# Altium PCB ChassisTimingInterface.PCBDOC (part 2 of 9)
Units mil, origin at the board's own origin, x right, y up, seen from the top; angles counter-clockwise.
Board outline 7007.87 x 4368.85 mil, 10 copper layers (Top Layer, Int1 (GND), Int2 (Sign), Int3 (Sign), Int4 (PWR), Int5 (GND), Int6 (Sign), Int7 (Sign), Int8 (GND), Bottom Layer), stack 54.89 mil thick; 537 components, 525 nets, 2288 pads, 1306 vias.
Unrouted connection lines stored in the file: 373.
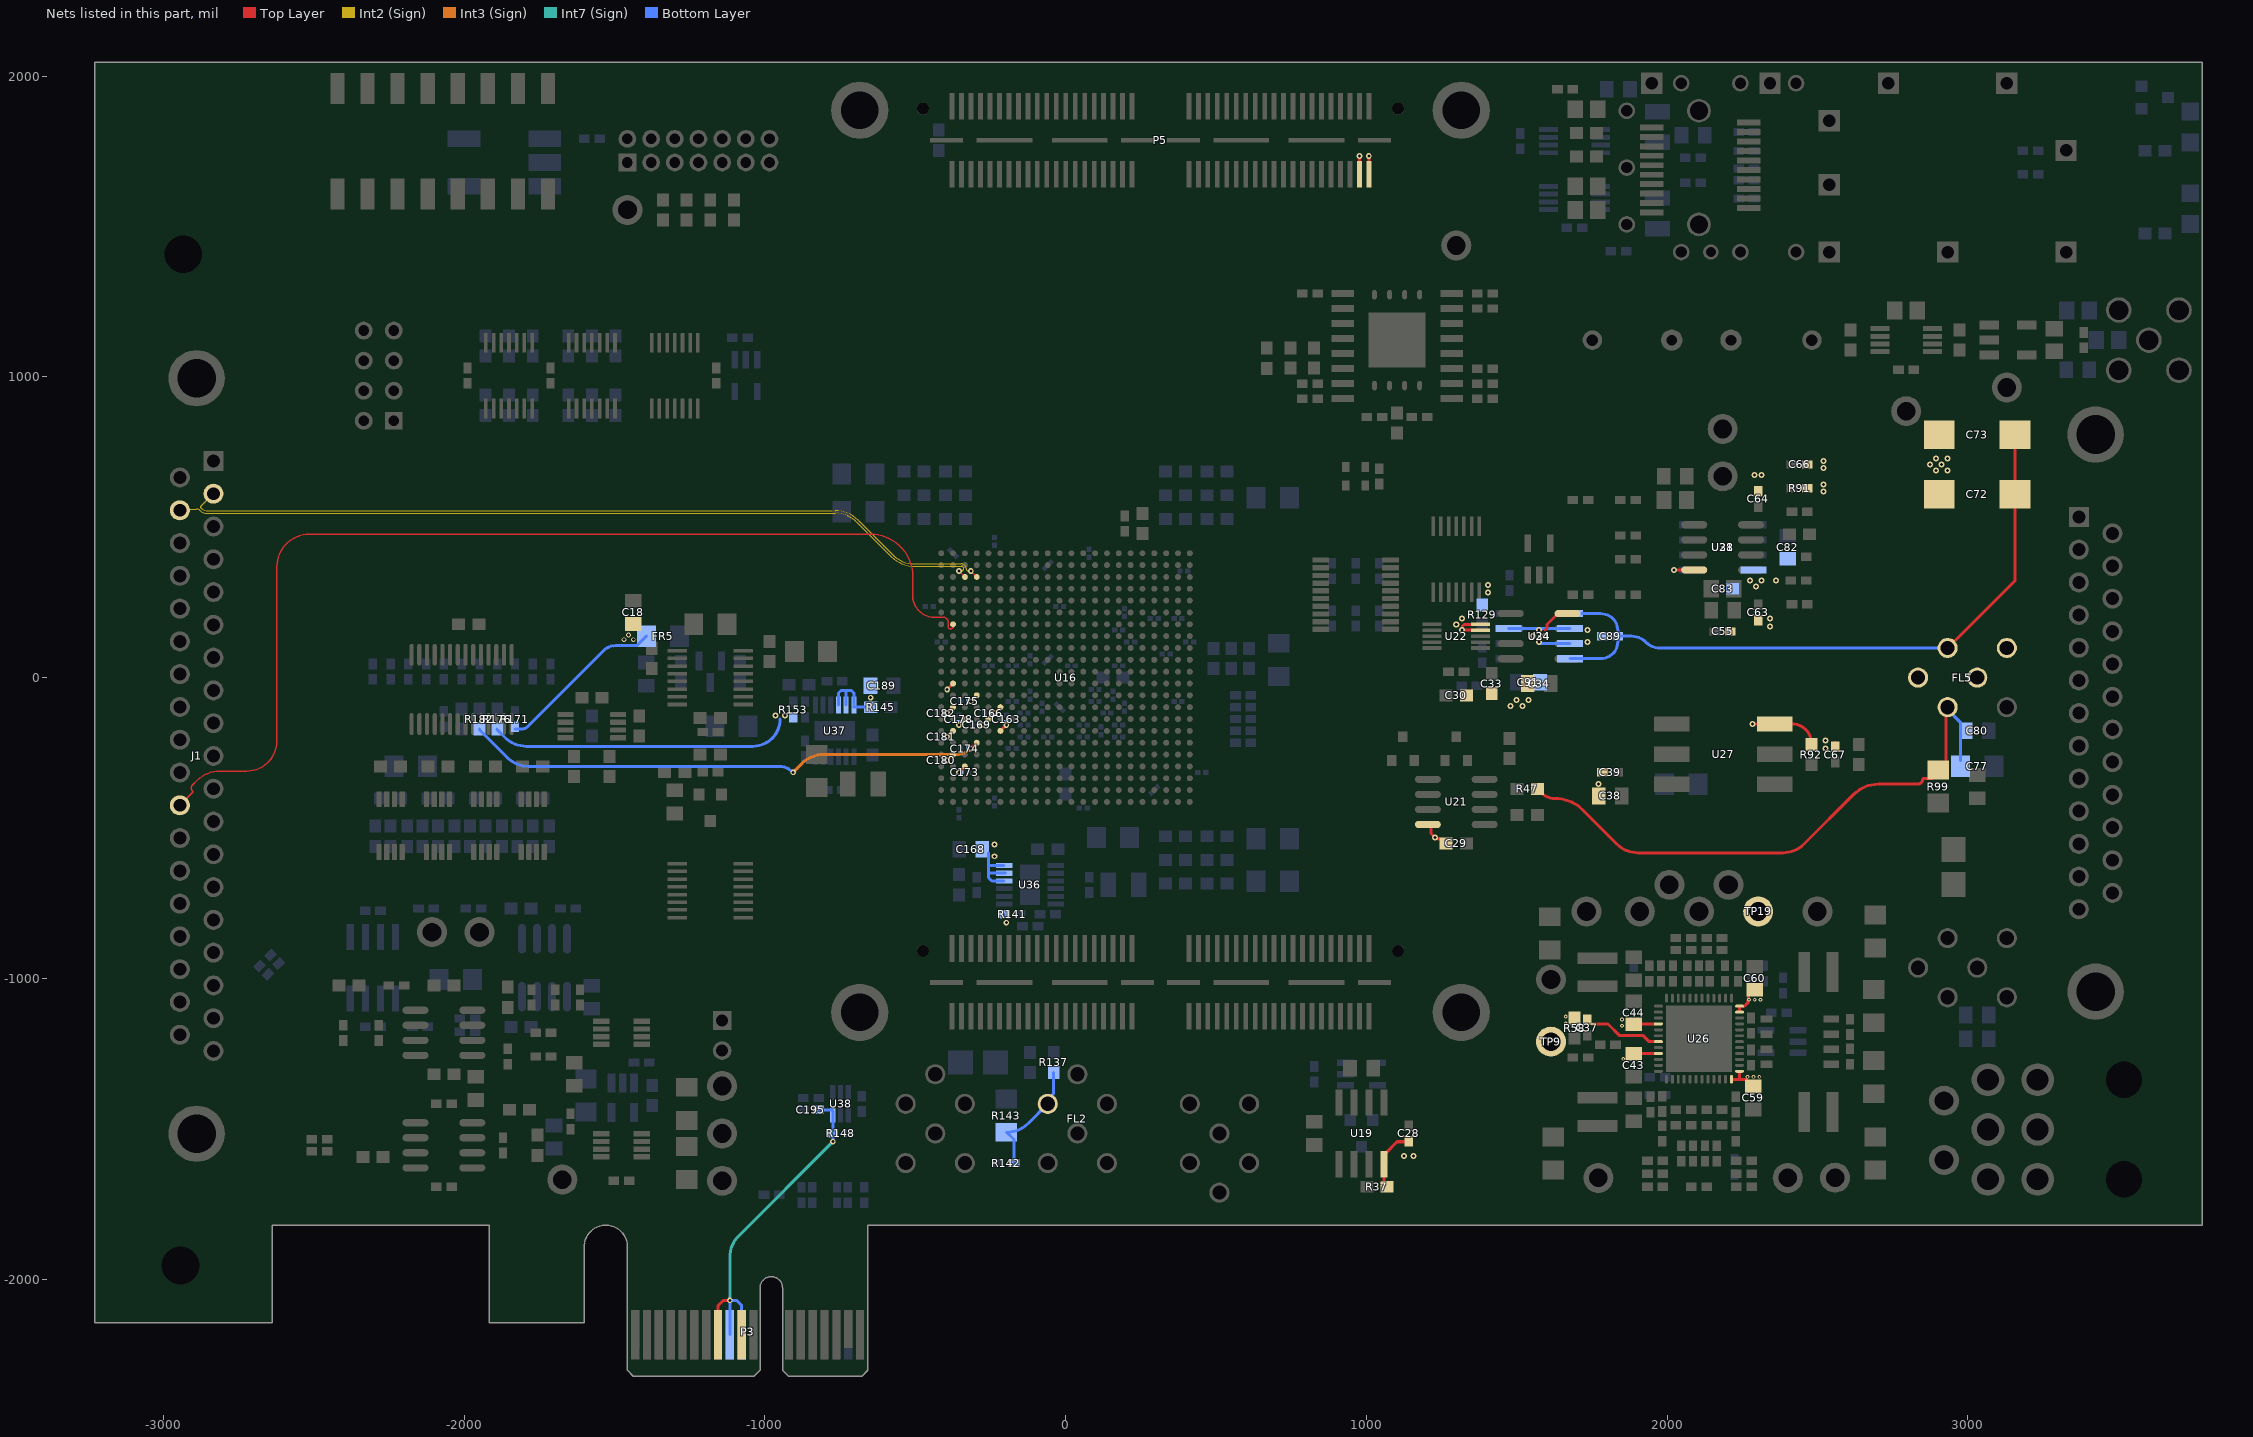
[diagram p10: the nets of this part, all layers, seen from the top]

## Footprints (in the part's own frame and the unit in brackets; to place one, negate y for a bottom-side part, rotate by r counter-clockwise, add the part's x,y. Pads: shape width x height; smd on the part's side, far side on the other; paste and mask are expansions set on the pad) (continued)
CP-48-13_L [mm] "QFN, 48-Leads, Body 7x7mm, Pitch 0.5mm, Thermal Pad 5.6x5.6mm, IPC High Density"
  oval 0.75x0.25 smd: 1(-3.425,2.75) 2(-3.425,2.25) 3(-3.425,1.75) 4(-3.425,1.25) 5(-3.425,0.75) 6(-3.425,0.25) 7(-3.425,-0.25) 8(-3.425,-0.75) 9(-3.425,-1.25) 10(-3.425,-1.75) 11(-3.425,-2.25) 12(-3.425,-2.75) 25(3.425,-2.75) 26(3.425,-2.25) 27(3.425,-1.75) 28(3.425,-1.25) 29(3.425,-0.75) 30(3.425,-0.25) 31(3.425,0.25) 32(3.425,0.75) 33(3.425,1.25) 34(3.425,1.75) 35(3.425,2.25) 36(3.425,2.75)
  oval 0.25x0.75 smd: 13(-2.75,-3.425) 14(-2.25,-3.425) 15(-1.75,-3.425) 16(-1.25,-3.425) 17(-0.75,-3.425) 18(-0.25,-3.425) 19(0.25,-3.425) 20(0.75,-3.425) 21(1.25,-3.425) 22(1.75,-3.425) 23(2.25,-3.425) 24(2.75,-3.425) 37(2.75,3.425) 38(2.25,3.425) 39(1.75,3.425) 40(1.25,3.425) 41(0.75,3.425) 42(0.25,3.425) 43(-0.25,3.425) 44(-0.75,3.425) 45(-1.25,3.425) 46(-1.75,3.425) 47(-2.25,3.425) 48(-2.75,3.425)
  rect 5.6x5.6 smd: 49(0,0)
  silkscreen extent -4.47,-3.7 3.7,3.7, body extent -3.55,-3.55 3.55,3.55, height 0.8
CR1005-0402 [mm] "Chip Resistor; Body 1.1 x 0.5 mm (LxW typ)"
  rect 0.9x0.7 smd: 1(-0.65,0) 2(0.65,0)
  body extent -0.5,-0.25 0.5,0.25, height 0.32
CR1608-0603 [mm] "Chip Resistor; Body 1.6 x 0.8 mm (LxW typ)"
  rect 1.1x1 smd: 1(-0.85,0) 2(0.85,0)
  body extent -0.76,-0.43 0.79,0.42, height 0.46
CR2012-0805 [mm] "Chip Resistor; Body 2.0 x 1.3 mm (LxW typ)"
  rect 1.3x1.5 smd: 1(-0.95,0) 2(0.95,0)
  body extent -1,-0.62 1,0.63, height 0.46
DB25F-RA [mm] "Receptiacle; D Subminiature 25 Position; Right Angle"
  rect 1.69x1.69 hole 1.09: 1(-16.566,-1.42)
  round 1.69 hole 1.09: 2(-13.805,-1.42) 3(-11.044,-1.42) 4(-8.283,-1.42) 5(-5.522,-1.42) 6(-2.761,-1.42) 7(0,-1.42) 8(2.761,-1.42) 9(5.522,-1.42) 10(8.283,-1.42) 11(11.044,-1.42) 12(13.805,-1.42) 13(16.566,-1.42) 14(-15.185,1.42) 15(-12.424,1.42) 16(-9.663,1.42) 17(-6.902,1.42) 18(-4.142,1.42) 19(-1.381,1.42) 20(1.381,1.42) 21(4.142,1.42) 22(6.903,1.42) 23(9.664,1.42) 24(12.425,1.42) 25(15.186,1.42)
  round 4.76 hole 3.26: 26(-23.526,0) 27(23.526,0)
  silkscreen extent -26.5,-3 26.6,9.5, body extent -26.59,-3.18 26.49,15.72, height 12.62
DB37M-RA [mm] "Plug; D Subminiature 37 Position; Right Angle"
  rect 1.69x1.69 hole 1.09: 1(24.917,-1.42)
  round 1.69 hole 1.09: 2(22.149,-1.42) 3(19.38,-1.42) 4(16.612,-1.42) 5(13.843,-1.42) 6(11.074,-1.42) 7(8.306,-1.42) 8(5.537,-1.42) 9(2.769,-1.42) 10(0,-1.42) 11(-2.769,-1.42) 12(-5.537,-1.42) 13(-8.306,-1.42) 14(-11.074,-1.42) 15(-13.843,-1.42) 16(-16.612,-1.42) 17(-19.38,-1.42) 18(-22.149,-1.42) 19(-24.917,-1.42) 20(23.52,1.42) 21(20.752,1.42) 22(17.983,1.42) 23(15.215,1.42) 24(12.446,1.42) 25(9.677,1.42) 26(6.909,1.42) 27(4.14,1.42) 28(1.372,1.42) 29(-1.397,1.42) 30(-4.166,1.42) 31(-6.934,1.42) 32(-9.703,1.42) 33(-12.471,1.42) 34(-15.24,1.42) 35(-18.009,1.42) 36(-20.777,1.42) 37(-23.546,1.42)
  round 4.76 hole 3.26: 38(31.902,0) 39(-31.902,0)
  silkscreen extent -35.08,-3.05 35.08,9.52, body extent -34.77,-3.24 34.77,15.37, height 12.62
DGK0008A_N [mm] "TSOP, 8-Leads, Body 3.1x3.1mm, Pitch 0.65mm, IPC Medium Density"
  rrect22% 1.35x0.45 smd: 1(-2.225,0.975) 2(-2.225,0.325) 3(-2.225,-0.325) 4(-2.225,-0.975) 5(2.225,-0.975) 6(2.225,-0.325) 7(2.225,0.325) 8(2.225,0.975)
  silkscreen extent -2.35,-1.55 1.15,1.9, body extent -2.45,-1.5 2.45,1.5, height 0.94
DIP_SW_8WAY_SMD_SIDE [mm] "DIP Switch; 16 Leads, right-angle"
  rect 1.2x2.6 smd: 1(-8.89,-4.45) 2(-6.35,-4.45) 3(-3.81,-4.45) 4(-1.27,-4.45) 5(1.27,-4.45) 6(3.81,-4.45) 7(6.35,-4.45) 8(8.89,-4.45) 9(8.89,4.45) 10(6.35,4.45) 11(3.81,4.45) 12(1.27,4.45) 13(-1.27,4.45) 14(-3.81,4.45) 15(-6.35,4.45) 16(-8.89,4.45)
  silkscreen extent -10.29,-2.5 10.31,2.5, body extent -11.15,-6.5 11.15,4.65, height 6.98
ECQPZ120060-5.0 [mm] "Polypropylene Film Capacitor; Body 12.0 x 6.0 mm (LxW typ); 5.0mm lead spacing"
  round 1.8 hole 0.9: 1(0,0) 2(5,0)
  silkscreen extent -3.5,-3 8.5,3
FGG484 [mm] "BGA, 484-Balls, Body 23x23mm, Pitch 1mm"
  round 0.5 smd: A1(-10.5,10.5) A2(-9.5,10.5) A3(-8.5,10.5) A4(-7.5,10.5) A5(-6.5,10.5) A6(-5.5,10.5) A7(-4.5,10.5) A8(-3.5,10.5) A9(-2.5,10.5) A10(-1.5,10.5) A11(-0.5,10.5) A12(0.5,10.5) A13(1.5,10.5) A14(2.5,10.5) A15(3.5,10.5) A16(4.5,10.5) A17(5.5,10.5) A18(6.5,10.5) A19(7.5,10.5) A20(8.5,10.5) A21(9.5,10.5) A22(10.5,10.5) AA1(-10.5,-9.5) AA2(-9.5,-9.5) AA3(-8.5,-9.5) AA4(-7.5,-9.5) AA5(-6.5,-9.5) AA6(-5.5,-9.5) AA7(-4.5,-9.5) AA8(-3.5,-9.5) AA9(-2.5,-9.5) AA10(-1.5,-9.5) AA11(-0.5,-9.5) AA12(0.5,-9.5) AA13(1.5,-9.5) AA14(2.5,-9.5) AA15(3.5,-9.5) AA16(4.5,-9.5) AA17(5.5,-9.5) AA18(6.5,-9.5) AA19(7.5,-9.5) AA20(8.5,-9.5) AA21(9.5,-9.5) AA22(10.5,-9.5) AB1(-10.5,-10.5) AB2(-9.5,-10.5) AB3(-8.5,-10.5) AB4(-7.5,-10.5) AB5(-6.5,-10.5) AB6(-5.5,-10.5) AB7(-4.5,-10.5) AB8(-3.5,-10.5) AB9(-2.5,-10.5) AB10(-1.5,-10.5) AB11(-0.5,-10.5) AB12(0.5,-10.5) AB13(1.5,-10.5) AB14(2.5,-10.5) AB15(3.5,-10.5) AB16(4.5,-10.5) AB17(5.5,-10.5) AB18(6.5,-10.5) AB19(7.5,-10.5) AB20(8.5,-10.5) AB21(9.5,-10.5) AB22(10.5,-10.5) B1(-10.5,9.5) B2(-9.5,9.5) B3(-8.5,9.5) B4(-7.5,9.5) B5(-6.5,9.5) B6(-5.5,9.5) B7(-4.5,9.5) B8(-3.5,9.5) B9(-2.5,9.5) B10(-1.5,9.5) B11(-0.5,9.5) B12(0.5,9.5) B13(1.5,9.5) B14(2.5,9.5) B15(3.5,9.5) B16(4.5,9.5) B17(5.5,9.5) B18(6.5,9.5) B19(7.5,9.5) B20(8.5,9.5) B21(9.5,9.5) B22(10.5,9.5) C1(-10.5,8.5) C2(-9.5,8.5) C3(-8.5,8.5) C4(-7.5,8.5) C5(-6.5,8.5) C6(-5.5,8.5) C7(-4.5,8.5) C8(-3.5,8.5) C9(-2.5,8.5) C10(-1.5,8.5) C11(-0.5,8.5) C12(0.5,8.5) C13(1.5,8.5) C14(2.5,8.5) C15(3.5,8.5) C16(4.5,8.5) C17(5.5,8.5) C18(6.5,8.5) C19(7.5,8.5) C20(8.5,8.5) C21(9.5,8.5) C22(10.5,8.5) D1(-10.5,7.5) D2(-9.5,7.5) D3(-8.5,7.5) D4(-7.5,7.5) D5(-6.5,7.5) D6(-5.5,7.5) D7(-4.5,7.5) D8(-3.5,7.5) D9(-2.5,7.5) D10(-1.5,7.5) D11(-0.5,7.5) D12(0.5,7.5) D13(1.5,7.5) D14(2.5,7.5) D15(3.5,7.5) D16(4.5,7.5) D17(5.5,7.5) D18(6.5,7.5) D19(7.5,7.5) D20(8.5,7.5) D21(9.5,7.5) D22(10.5,7.5) E1(-10.5,6.5) E2(-9.5,6.5) E3(-8.5,6.5) E4(-7.5,6.5) E5(-6.5,6.5) E6(-5.5,6.5) E7(-4.5,6.5) E8(-3.5,6.5) E9(-2.5,6.5) E10(-1.5,6.5) E11(-0.5,6.5) E12(0.5,6.5) E13(1.5,6.5) E14(2.5,6.5) E15(3.5,6.5) E16(4.5,6.5) E17(5.5,6.5) E18(6.5,6.5) E19(7.5,6.5) E20(8.5,6.5) E21(9.5,6.5) E22(10.5,6.5) F1(-10.5,5.5) F2(-9.5,5.5) F3(-8.5,5.5) F4(-7.5,5.5) F5(-6.5,5.5) F6(-5.5,5.5) F7(-4.5,5.5) F8(-3.5,5.5) F9(-2.5,5.5) F10(-1.5,5.5) F11(-0.5,5.5) F12(0.5,5.5) F13(1.5,5.5) F14(2.5,5.5) F15(3.5,5.5) F16(4.5,5.5) F17(5.5,5.5) F18(6.5,5.5) F19(7.5,5.5) F20(8.5,5.5) F21(9.5,5.5) F22(10.5,5.5) G1(-10.5,4.5) G2(-9.5,4.5) G3(-8.5,4.5) G4(-7.5,4.5) G5(-6.5,4.5) G6(-5.5,4.5) G7(-4.5,4.5) G8(-3.5,4.5) G9(-2.5,4.5) G10(-1.5,4.5) G11(-0.5,4.5) G12(0.5,4.5) G13(1.5,4.5) G14(2.5,4.5) G15(3.5,4.5) G16(4.5,4.5) G17(5.5,4.5) G18(6.5,4.5) G19(7.5,4.5) G20(8.5,4.5) G21(9.5,4.5) G22(10.5,4.5) H1(-10.5,3.5) H2(-9.5,3.5) H3(-8.5,3.5) H4(-7.5,3.5) H5(-6.5,3.5) H6(-5.5,3.5) H7(-4.5,3.5) H8(-3.5,3.5) H9(-2.5,3.5) H10(-1.5,3.5) H11(-0.5,3.5) H12(0.5,3.5) H13(1.5,3.5) H14(2.5,3.5) H15(3.5,3.5) H16(4.5,3.5) H17(5.5,3.5) H18(6.5,3.5) H19(7.5,3.5) H20(8.5,3.5) H21(9.5,3.5) H22(10.5,3.5) J1(-10.5,2.5) J2(-9.5,2.5) J3(-8.5,2.5) J4(-7.5,2.5) J5(-6.5,2.5) J6(-5.5,2.5) J7(-4.5,2.5) J8(-3.5,2.5) J9(-2.5,2.5) J10(-1.5,2.5) J11(-0.5,2.5) J12(0.5,2.5) J13(1.5,2.5) J14(2.5,2.5) J15(3.5,2.5) J16(4.5,2.5) J17(5.5,2.5) J18(6.5,2.5) J19(7.5,2.5) J20(8.5,2.5) J21(9.5,2.5) J22(10.5,2.5) K1(-10.5,1.5) K2(-9.5,1.5) K3(-8.5,1.5) K4(-7.5,1.5) K5(-6.5,1.5) K6(-5.5,1.5) K7(-4.5,1.5) K8(-3.5,1.5) K9(-2.5,1.5) K10(-1.5,1.5) K11(-0.5,1.5) K12(0.5,1.5) K13(1.5,1.5) K14(2.5,1.5) K15(3.5,1.5) K16(4.5,1.5) K17(5.5,1.5) K18(6.5,1.5) K19(7.5,1.5) K20(8.5,1.5) K21(9.5,1.5) K22(10.5,1.5) L1(-10.5,0.5) L2(-9.5,0.5) L3(-8.5,0.5) L4(-7.5,0.5) L5(-6.5,0.5) L6(-5.5,0.5) L7(-4.5,0.5) L8(-3.5,0.5) L9(-2.5,0.5) L10(-1.5,0.5) L11(-0.5,0.5) L12(0.5,0.5) L13(1.5,0.5) L14(2.5,0.5) L15(3.5,0.5) L16(4.5,0.5) L17(5.5,0.5) L18(6.5,0.5) L19(7.5,0.5) L20(8.5,0.5) L21(9.5,0.5) L22(10.5,0.5) M1(-10.5,-0.5) M2(-9.5,-0.5) M3(-8.5,-0.5) M4(-7.5,-0.5) M5(-6.5,-0.5) M6(-5.5,-0.5) M7(-4.5,-0.5) M8(-3.5,-0.5) M9(-2.5,-0.5) M10(-1.5,-0.5) M11(-0.5,-0.5) M12(0.5,-0.5) M13(1.5,-0.5) M14(2.5,-0.5) M15(3.5,-0.5) M16(4.5,-0.5) M17(5.5,-0.5) M18(6.5,-0.5) M19(7.5,-0.5) M20(8.5,-0.5) M21(9.5,-0.5) M22(10.5,-0.5) N1(-10.5,-1.5) N2(-9.5,-1.5) N3(-8.5,-1.5) N4(-7.5,-1.5) N5(-6.5,-1.5) N6(-5.5,-1.5) N7(-4.5,-1.5) N8(-3.5,-1.5) N9(-2.5,-1.5) N10(-1.5,-1.5) N11(-0.5,-1.5) N12(0.5,-1.5) N13(1.5,-1.5) N14(2.5,-1.5) N15(3.5,-1.5) N16(4.5,-1.5) N17(5.5,-1.5) N18(6.5,-1.5) N19(7.5,-1.5) N20(8.5,-1.5) N21(9.5,-1.5) N22(10.5,-1.5) P1(-10.5,-2.5) P2(-9.5,-2.5) P3(-8.5,-2.5) P4(-7.5,-2.5) P5(-6.5,-2.5) P6(-5.5,-2.5) P7(-4.5,-2.5) P8(-3.5,-2.5) P9(-2.5,-2.5) P10(-1.5,-2.5) P11(-0.5,-2.5) P12(0.5,-2.5) P13(1.5,-2.5) P14(2.5,-2.5) P15(3.5,-2.5) P16(4.5,-2.5) P17(5.5,-2.5) P18(6.5,-2.5) P19(7.5,-2.5) P20(8.5,-2.5) P21(9.5,-2.5) P22(10.5,-2.5) R1(-10.5,-3.5) R2(-9.5,-3.5) R3(-8.5,-3.5) R4(-7.5,-3.5) R5(-6.5,-3.5) R6(-5.5,-3.5) R7(-4.5,-3.5) R8(-3.5,-3.5) R9(-2.5,-3.5) R10(-1.5,-3.5) R11(-0.5,-3.5) R12(0.5,-3.5) R13(1.5,-3.5) R14(2.5,-3.5) R15(3.5,-3.5) R16(4.5,-3.5) R17(5.5,-3.5) R18(6.5,-3.5) R19(7.5,-3.5) R20(8.5,-3.5) R21(9.5,-3.5) R22(10.5,-3.5) T1(-10.5,-4.5) T2(-9.5,-4.5) T3(-8.5,-4.5) T4(-7.5,-4.5) T5(-6.5,-4.5) T6(-5.5,-4.5) T7(-4.5,-4.5) T8(-3.5,-4.5) T9(-2.5,-4.5) T10(-1.5,-4.5) T11(-0.5,-4.5) T12(0.5,-4.5) T13(1.5,-4.5) T14(2.5,-4.5) T15(3.5,-4.5) T16(4.5,-4.5) T17(5.5,-4.5) T18(6.5,-4.5) T19(7.5,-4.5) T20(8.5,-4.5) T21(9.5,-4.5) T22(10.5,-4.5) U1(-10.5,-5.5) U2(-9.5,-5.5) U3(-8.5,-5.5) U4(-7.5,-5.5) U5(-6.5,-5.5) U6(-5.5,-5.5) U7(-4.5,-5.5) U8(-3.5,-5.5) U9(-2.5,-5.5) U10(-1.5,-5.5) U11(-0.5,-5.5) U12(0.5,-5.5) U13(1.5,-5.5) U14(2.5,-5.5) U15(3.5,-5.5) U16(4.5,-5.5) U17(5.5,-5.5) U18(6.5,-5.5) U19(7.5,-5.5) U20(8.5,-5.5) U21(9.5,-5.5) U22(10.5,-5.5) V1(-10.5,-6.5) V2(-9.5,-6.5) V3(-8.5,-6.5) V4(-7.5,-6.5) V5(-6.5,-6.5) V6(-5.5,-6.5) V7(-4.5,-6.5) V8(-3.5,-6.5) V9(-2.5,-6.5) V10(-1.5,-6.5) V11(-0.5,-6.5) V12(0.5,-6.5) V13(1.5,-6.5) V14(2.5,-6.5) V15(3.5,-6.5) V16(4.5,-6.5) V17(5.5,-6.5) V18(6.5,-6.5) V19(7.5,-6.5) V20(8.5,-6.5) V21(9.5,-6.5) V22(10.5,-6.5) W1(-10.5,-7.5) W2(-9.5,-7.5) W3(-8.5,-7.5) W4(-7.5,-7.5) W5(-6.5,-7.5) W6(-5.5,-7.5) W7(-4.5,-7.5) W8(-3.5,-7.5) W9(-2.5,-7.5) W10(-1.5,-7.5) W11(-0.5,-7.5) W12(0.5,-7.5) W13(1.5,-7.5) W14(2.5,-7.5) W15(3.5,-7.5) W16(4.5,-7.5) W17(5.5,-7.5) W18(6.5,-7.5) W19(7.5,-7.5) W20(8.5,-7.5) W21(9.5,-7.5) W22(10.5,-7.5) Y1(-10.5,-8.5) Y2(-9.5,-8.5) Y3(-8.5,-8.5) Y4(-7.5,-8.5) Y5(-6.5,-8.5) Y6(-5.5,-8.5) Y7(-4.5,-8.5) Y8(-3.5,-8.5) Y9(-2.5,-8.5) Y10(-1.5,-8.5) Y11(-0.5,-8.5) Y12(0.5,-8.5) Y13(1.5,-8.5) Y14(2.5,-8.5) Y15(3.5,-8.5) Y16(4.5,-8.5) Y17(5.5,-8.5) Y18(6.5,-8.5) Y19(7.5,-8.5) Y20(8.5,-8.5) Y21(9.5,-8.5) Y22(10.5,-8.5)
  silkscreen extent -12.27,-11.5 11.5,11.5, body extent -11.5,-11.5 11.5,11.5, height 2.6
FP-002-15547-MFG [mm]
  rect 1.9x0.6 smd: 1(-4.6,4.445) 2(-4.6,3.175) 3(-4.6,1.905) 4(-4.6,0.635) 5(-4.6,-0.635) 6(-4.6,-1.905) 7(-4.6,-3.175) 8(-4.6,-4.445) 9(4.6,-4.445) 10(4.6,-3.175) 11(4.6,-1.905) 12(4.6,-0.635) 13(4.6,0.635) 14(4.6,1.905) 15(4.6,3.175) 16(4.6,4.445)
  silkscreen extent -6.25,-5.25 2.8,5.25, body extent -5.65,-5.5 5.65,5.5, height 0.25
FP-CDFN2520-4LD-PL-1-MFG [mm]
  rect 0.85x0.65 smd paste+0 mask+0: 1(-0.775,0.825) 2(-0.775,-0.825) 3(0.775,-0.825) 4(0.775,0.825)
  silkscreen extent -1.92,-0.13 1.02,0.95, body extent -1.3,-1.38 1.3,1.38, height 0.25
FP-XAL40-MFG [mm]
  rect 0.98x3.4 smd: 1(-1.185,0) 2(1.185,0)
  silkscreen extent -2.15,-2.15 2.15,2.15, body extent -2.25,-2.25 2.25,2.25, height 0.25
KING-LED2107-13-RED-2_V [mm] "LED, Right Angle SMT, 2.1x0.7mm, 1.3mm Thickness, Pad 1 Cathode"
  rect 1.5x1.5 smd paste+0 mask+0: 1(1.3,0) 2(-1.3,0)
  silkscreen extent 2.35,-0.64 2.35,0.63, body extent -1.05,-0.4 1.05,0.9, height 0.67
LED-0805 [mm] "SMD LED, 805, Body 2.0 x 1.3 mm (LxW typ)"
  rect 1.15x1.4 smd: 1(-0.975,0) 2(0.975,0)
  silkscreen extent -1.85,-0.6 -1.85,0.6, body extent -1,-0.62 1,0.63, height 0.75
LIGO-LOGO-SM [mil] "Smaller Ligo Logo"
  silkscreen extent -154,4 -36,122
LT-S5-5-TSOT-23_M [mm] "SOT23, 5-Leads, Body 2.90x1.63mm, Pitch 0.95mm, IPC Low Density"
  rect 1.6x0.65 smd: 1(-1.25,0.95) 2(-1.25,0) 3(-1.25,-0.95) 4(1.25,-0.95) 5(1.25,0.95)
  silkscreen extent -1.37,-1.45 0.05,1.95, body extent -0.87,-1.45 0.87,1.45, height 1
MCSM-DO-214BA-2_L [mm] "Molded, 2-Leads, Body 4.57x3.94mm, IPC High Density"
  rect 2.1x2.05 smd: 1(-1.475,0) 2(1.475,0)
  silkscreen extent -2.3,-2 3.03,2, body extent -2.5,-1.97 2.51,1.97, height 3.3
MSA/SFP2x10 [mm] "Multi Source Agreement, Small Factor Plugable"
  rect 2x0.5 smd: 1(0,0) 2(0,-0.8) 3(0,-1.6) 4(0,-2.4) 5(0,-3.2) 6(0,-4) 7(0,-4.8) 8(0,-5.6) 9(0,-6.4) 10(0,-7.2) 11(8.2,-6.8) 12(8.2,-6) 13(8.2,-5.2) 14(8.2,-4.4) 15(8.2,-3.6) 16(8.2,-2.8) 17(8.2,-2) 18(8.2,-1.2) 19(8.2,-0.4) 20(8.2,0.4)
  rect 1.8x1.8 hole 1.05: 21(-26.8,-4.85) 21(-26.8,3.73) 21(-21.8,-10.53) 21(-16.8,3.73) 21(-11.8,-10.53) 21(-6.8,-1.95) 21(-6.8,3.73) 21(-6.8,-7.35) 21(-1.8,-10.53) 21(8.2,-10.53)
  round 1.4 hole 0.95: 22(-4,3.73) 22(-4,-10.53) 22(0.7,3.73) 22(0.7,-10.53) 22(5.7,3.73) 22(5.7,-10.53) 22(10.3,-3.4) 22(10.3,1.4) 22(10.3,-8.2)
  round 2 hole 1.55: 23(4.2,1.4) 23(4.2,-8.2)
  round 1.3 hole 0.85: 24(3.2,3.73)
  silkscreen extent -31.2,-11.43 10.9,4.63, body extent -38.26,-11.3 10.54,4.54, height 10.83
MSOP8 [mm] "MSOP Plastic Small-Outline Package"
  rect 0.42x1.6 smd: 1(-0.975,-2.205) 2(-0.325,-2.205) 3(0.325,-2.205) 4(0.975,-2.205) 5(0.975,2.195) 6(0.325,2.195) 7(-0.325,2.195) 8(-0.975,2.195)
  silkscreen extent -1.3,-0.77 1.3,0.76, body extent -1.5,-2.45 1.5,2.45, height 1.15
MSOP12_PAD [mil] "MSOP 12 with pad"
  rect 55x17 smd: 1(-86,63.98) 2(-86,38.39) 3(-86,12.8) 4(-86,-12.8) 5(-86,-38.39) 6(-86,-63.98) 7(86,-63.98) 8(86,-38.39) 9(86,-12.8) 10(86,12.8) 11(86,38.39) 12(86,63.98)
  rect 65x133.86 smd: 13(0,0)
  silkscreen extent -53,-84 134,84, body extent -99,-79 99,79, height 67
MURA-BNX016-01_V [mm] "THD, 6-Leads, Body 12x11mm"
  round 1.7 hole 1.2: 1(-2.5,2.5) 2(2.5,2.5) 3(-2.5,-2.5) 4(2.5,-2.5) 5(0,0) 6(0,5)
  silkscreen extent -6.29,-6 5.5,6, body extent -5.5,-6 5.5,6, height 8
NETTIE1_BOTH [mm] "Tie two nets together"
  rect 1.575x1.575 hole 1.016: 1(0,0)
  round 1.575 hole 1.016: 2(2.54,0)
  Top Layer region: -1.016,-1.015 3.556,-1.015 3.556,1.017 -1.016,1.017
  Bottom Layer region: -1.016,-1.015 3.556,-1.015 3.556,1.017 -1.016,1.017
NETTIE1_SMDTOP [mil] "Tie two nets together"
  rect 10x10 smd mask-10: 1(0,0) 2(20,0)
  Top Layer region: -10,10 30,10 30,-10 -10,-10
ONSC-SOT-23-3-318-08_V [mm] "SOT23, 3-Leads, Body 2.92x1.3mm, Pitch 0.95mm"
  rect 0.9x0.8 smd: 1(-1,0.95) 2(-1,-0.95) 3(1,0)
  silkscreen extent -1.12,-1.46 0.65,2.02, body extent -0.65,-1.46 0.65,1.46, height 1.11
PCIeX1-GF-2D-1000-1K-O36 [mm] "Golden finger, PCIeX1, Dual, Opposite, Pitch 1mm, 36-Position"
  rect 0.7x3.2 smd far side: A1(-9.5,0.5)
  rect 0.7x4.2 smd far side: A2(-8.5,0) A3(-7.5,0) A4(-6.5,0) A5(-5.5,0) A6(-4.5,0) A7(-3.5,0) A8(-2.5,0) A9(-1.5,0) A10(-0.5,0) A11(0.5,0) A12(3.5,0) A13(4.5,0) A14(5.5,0) A15(6.5,0) A16(7.5,0) A17(8.5,0) A18(9.5,0)
  rect 0.7x4.2 smd: B1(-9.5,0) B2(-8.5,0) B3(-7.5,0) B4(-6.5,0) B5(-5.5,0) B6(-4.5,0) B7(-3.5,0) B8(-2.5,0) B9(-1.5,0) B10(-0.5,0) B11(0.5,0) B12(3.5,0) B13(4.5,0) B14(5.5,0) B15(6.5,0) B16(7.5,0) B18(9.5,0)
  rect 0.7x3.2 smd: B17(8.5,0.5)
PW0020A_N [mm] "SOP, 20-Leads, Body 6.6x4.5mm, Pitch 0.65mm, IPC Medium Density"
  rrect22% 1.4x0.45 smd: 1(-2.95,2.925) 2(-2.95,2.275) 3(-2.95,1.625) 4(-2.95,0.975) 5(-2.95,0.325) 6(-2.95,-0.325) 7(-2.95,-0.975) 8(-2.95,-1.625) 9(-2.95,-2.275) 10(-2.95,-2.925) 11(2.95,-2.925) 12(2.95,-2.275) 13(2.95,-1.625) 14(2.95,-0.975) 15(2.95,-0.325) 16(2.95,0.325) 17(2.95,0.975) 18(2.95,1.625) 19(2.95,2.275) 20(2.95,2.925)
  silkscreen extent -3.07,-3.3 1.85,3.82, body extent -3.21,-3.25 3.21,3.25, height 1
QSE040 [mil] "Samtec hi-speed socket, 0.8mm, QSE series, 80 pins"
  rect 16x89 smd: 1(-692.9,-112.78) 2(-692.9,112.78) 3(-661.42,-112.78) 4(-661.42,112.78) 5(-629.92,-112.78) 6(-629.92,112.78) 7(-598.42,-112.78) 8(-598.42,112.78) 9(-566.92,-112.78) 10(-566.92,112.78) 11(-535.42,-112.78) 12(-535.42,112.78) 13(-503.93,-112.78) 14(-503.93,112.78) 15(-472.43,-112.78) 16(-472.43,112.78) 17(-440.93,-112.78) 18(-440.93,112.78) 19(-409.43,-112.78) 20(-409.43,112.78) 21(-377.95,-112.78) 22(-377.95,112.78) 23(-346.45,-112.78) 24(-346.45,112.78) 25(-314.95,-112.78) 26(-314.95,112.78) 27(-283.45,-112.78) 28(-283.45,112.78) 29(-251.97,-112.78) 30(-251.97,112.78) 31(-220.47,-112.78) 32(-220.47,112.78) 33(-188.97,-112.78) 34(-188.97,112.78) 35(-157.47,-112.78) 36(-157.47,112.78) 37(-125.98,-112.78) 38(-125.98,112.78) 39(-94.48,-112.78) 40(-94.48,112.78) 41(94.48,-112.78) 42(94.48,112.78) 43(125.98,-112.78) 44(125.98,112.78) 45(157.47,-112.78) 46(157.47,112.78) 47(188.97,-112.78) 48(188.97,112.78) 49(220.47,-112.78) 50(220.47,112.78) 51(251.97,-112.78) 52(251.97,112.78) 53(283.45,-112.78) 54(283.45,112.78) 55(314.95,-112.78) 56(314.95,112.78) 57(346.45,-112.78) 58(346.45,112.78) 59(377.95,-112.78) 60(377.95,112.78) 61(409.43,-112.78) 62(409.43,112.78) 63(440.93,-112.78) 64(440.93,112.78) 65(472.43,-112.78) 66(472.43,112.78) 67(503.93,-112.78) 68(503.93,112.78) 69(535.42,-112.78) 70(535.42,112.78) 71(566.92,-112.78) 72(566.92,112.78) 73(598.42,-112.78) 74(598.42,112.78) 75(629.92,-112.78) 76(629.92,112.78) 77(661.42,-112.78) 78(661.42,112.78) 79(692.9,-112.78) 80(692.9,112.78)
  rect 109x16 smd: 81(-711.22,0) 84(-76.17,0) 85(76.17,0) 88(711.22,0)
  rect 185x16 smd: 82(-518.7,0) 83(-268.7,0) 86(268.7,0) 87(518.7,0)
  round 40 / inner round 60 / far side round 60 hole 40: 89(-789.95,104.92) 90(789.95,104.92)
  silkscreen extent -821,-205 821,167, body extent -812,-148 813,147, height 120
SC70 [mm] "SC-70; 6 Leads"
  rect 0.45x1.25 smd: 1(-0.65,-0.95) 2(0,-0.95) 3(0.65,-0.95) 4(0.65,0.95) 5(0,0.95) 6(-0.65,0.95)
  silkscreen extent -1.27,-1.95 1.15,0.7, body extent -1.1,-1.2 1.1,1.2, height 1.1
SMA-RA [mil] "SMA right angle PCB"
  round 85 hole 65: 1(0,0) 2(-100,-100) 2(-100,100) 2(100,-100) 2(100,100)
  silkscreen extent -160,-160 160,160, body extent -125,-460 125,125, height 375
SO-8_N [mm] "SOIC, 8-Leads, Body 4.9x3.9mm, Pitch 1.27mm, IPC Medium Density"
  oval 2.2x0.6 smd: 1(-2.4,1.905) 2(-2.4,0.635) 3(-2.4,-0.635) 4(-2.4,-1.905) 5(2.4,-1.905) 6(2.4,-0.635) 7(2.4,0.635) 8(2.4,1.905)
  silkscreen extent -2.53,-2.5 0.9,2.88, body extent -1.95,-2.45 1.95,2.45, height 1.75
SO-G3/C2.25 [mm] "SOT-23; 3 Leads; Body 3.0 x 2.5 mm, inc. leads (LxW max)"
  rect 0.95x1 smd: 1(-0.95,-1.125) 2(0.95,-1.125) 3(0,1.125)
  silkscreen extent -2.1,-1.25 1.32,1.13, body extent -1.45,-1.4 1.45,1.4, height 1.3
SO-G5/E2.4 [mm] "Small Outline; 5 Leads; Body 3.6 x 3.6 mm, inc. leads (LxW max)"
  rect 0.55x1.45 smd: 1(-0.95,-1.35) 2(0,-1.35) 3(0.95,-1.35) 4(0.95,1.35) 5(-0.95,1.35)
  silkscreen extent -1.67,-2.52 1.55,1.2, body extent -1.45,-1.4 1.45,1.4, height 1.45
SO-G8 [mm] "Small Outline; 8 Leads; Body Width 3.9 mm; Pitch 1.27 mm"
  rect 0.6x2.2 smd: 1(-1.905,-2.6) 2(-0.635,-2.6) 3(0.635,-2.6) 4(1.905,-2.6) 5(1.905,2.6) 6(0.635,2.6) 7(-0.635,2.6) 8(-1.905,2.6)
  silkscreen extent -2.88,-2.72 2.5,1.1, body extent -2.47,-3.06 2.48,3.06, height 1.75
SPSN-WSON-8_L [mm] "SON, 8-Leads, Body 6.00x8.00mm, Pitch 1.27mm, Thermal Pad 4.80x4.65mm, IPC High Density"
  oval 0.8x0.4 smd: 1(-3.84,1.905) 2(-3.84,0.635) 3(-3.84,-0.635) 4(-3.84,-1.905) 5(3.84,-1.905) 6(3.84,-0.635) 7(3.84,0.635) 8(3.84,1.905)
  rect 4.65x4.8 smd: 9(0,0)
  silkscreen extent -4.6,-3.15 4.15,3.2, body extent -4,-3 4,3, height 0.8
SSO-G8/SM8 [mm] "SSOP; 8 Leads; Body Width 2.8 mm; Pitch 0.65 mm"
  rect 0.45x1.4 smd: 1(-0.975,-1.7) 2(-0.325,-1.7) 3(0.325,-1.7) 4(0.975,-1.7) 5(0.975,1.7) 6(0.325,1.7) 7(-0.325,1.7) 8(-0.975,1.7)
  silkscreen extent -1.87,-1.82 1.6,1.7
SW_SMD_6MM [mm]
  rect 2.75x1.4 smd: 1(0,0) 2(6.8,0) 3(0,-4) 4(6.8,-4) 5(0,-2)
  silkscreen extent -2.75,-5 6.38,1
TC7343-2917 [mm] "Capacitor, D Size, Tantalum; Body 7.3 x 4.3 mm (LxW typ)"
  rect 2.6x2.4 smd: 1(-3.2,0) 2(3.2,0)
  silkscreen extent -4.58,-2.3 3.8,2.42, body extent -3.7,-2.22 3.7,2.23
TI-DBZ3_N [mm] "SOT23, 3-Leads, Body 2.92x1.3 mm, Pitch 0.95 mm, IPC Medium Density"
  rect 1.6x0.6 smd: 1(-0.9,0.95) 2(-0.9,-0.95) 3(0.9,0)
  silkscreen extent -1.02,-1.5 0.7,1.92, body extent -0.7,-1.52 0.7,1.52, height 1.12
TP1-BLK#1 [mm] "Testpoint pin, black"
  round 2.54 hole 1.58: 1(0,0)
  body extent -1.27,-1.27 1.27,1.27, height 4.89
TP1-BLK#2 [mm] "Testpoint pin, black"
  round 2.54 hole 1.58: 1(0.312,0)
  body extent -1.27,-1.27 1.27,1.27, height 4.89
TP1-RED#1 [mm] "Testpoint pin, red"
  round 2.54 hole 1.58: 1(0,0)
  body extent -1.27,-1.27 1.27,1.27, height 4.89
TP1-RED#2 [mm] "Testpoint pin, red"
  round 2.54 hole 1.58: 1(0.312,0)
  body extent -1.27,-1.27 1.27,1.27, height 4.89
TP1-WHT [mm] "Testpoint pin, white"
  round 2.54 hole 1.58: 1(0,0)
  body extent -1.27,-1.27 1.27,1.27, height 4.89
TP1-YLW#1 [mm] "Testpoint pin, yellow"
  round 2.54 hole 1.58: 1(0,-0.05)
  body extent -1.27,-1.27 1.27,1.27, height 4.89
TP1-YLW#2 [mm] "Testpoint pin, yellow"
  round 2.54 hole 1.58: 1(0,0)
  body extent -1.27,-1.27 1.27,1.27, height 4.89
TSSO3x5-G10 [mm] "Shrink Small Outline; 10 Leads; Body Width 3 mm; Pitch 0.5 mm"
  rect 0.3x1.6 smd: 1(-1,-2.05) 2(-0.5,-2.05) 3(0,-2.05) 4(0.5,-2.05) 5(1,-2.05) 6(1,2.05) 7(0.5,2.05) 8(0,2.05) 9(-0.5,2.05) 10(-1,2.05)
  silkscreen extent -1.82,-2.18 1.58,0.85, body extent -1.5,-2.54 1.5,2.49, height 1.05
TSSOP14 [mm] "Shrink Small Outline; 14 Leads; Body Width 4.4 mm; Pitch 0.65 mm"
  rect 0.3x1.65 smd: 1(-1.95,-2.775) 2(-1.3,-2.775) 3(-0.65,-2.775) 4(0,-2.775) 5(0.65,-2.775) 6(1.3,-2.775) 7(1.95,-2.775) 8(1.95,2.775) 9(1.3,2.775) 10(0.65,2.775) 11(0,2.775) 12(-0.65,2.775) 13(-1.3,2.775) 14(-1.95,2.775)
  silkscreen extent -2.77,-2.9 2.55,1.55, body extent -2.5,-3.21 2.5,3.21, height 0.94
TSSOP16 [mm] "Shrink Small Outline; 16 Leads; Body Width 4.4 mm; Pitch 0.65 mm"
  rect 0.3x1.65 smd: 1(-2.275,-2.775) 2(-1.625,-2.775) 3(-0.975,-2.775) 4(-0.325,-2.775) 5(0.325,-2.775) 6(0.975,-2.775) 7(1.625,-2.775) 8(2.275,-2.775) 9(2.275,2.775) 10(1.625,2.775) 11(0.975,2.775) 12(0.325,2.775) 13(-0.325,2.775) 14(-0.975,2.775) 15(-1.625,2.775) 16(-2.275,2.775)
  silkscreen extent -3.1,-2.9 2.55,1.55, body extent -2.5,-3.2 2.5,3.2, height 1.13
VECTRON_C5310 [mm] "Vectron VCXO, C5310 series"
  rect 3x1.3 smd: 1(0,0) 2(0,-2.54) 3(0,-5.08) 4(8.7,-5.08) 5(8.7,-2.54) 6(8.7,0)
  silkscreen extent -2.56,-9.75 9.25,4.75, body extent -0.41,-9.65 9.14,4.65, height 5.9
VISH-POWERPAKSO-8_A_V [mm] "SMD, 8-Leads, Body 6.15x5.155mm, Pitch 1.27mm"
  rect 1.27x0.61 smd: 1(-2.67,1.905) 2(-2.67,0.635) 3(-2.67,-0.635) 4(-2.67,-1.905)
  rect 1.02x0.61 smd: 5(2.795,-1.905) 6(2.795,-0.635) 7(2.795,0.635) 8(2.795,1.905)
  Top Layer region: -1.215,-1.955 2.595,-1.955 2.595,-0.305 -1.215,-0.305
  Top Layer region: -1.215,0.305 2.595,0.305 2.595,1.955 -1.215,1.955
  silkscreen extent -3.98,1.78 -3.73,2.03, body extent -3.08,-2.58 3.08,2.58, height 1.12

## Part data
C1 C3 C11: library part ChipCap, "C0402 0.033nF", Part Number=490-13296-1-ND, Tolerance=10%
C2 C4 C5 C9 C10 C19 C24 C29 C30 C33 C68 C83 C130 C147 C150 C184 C192 C201 C202 C203 C207 C210 C211 C212 C214 C216: library part ChipCap, "C0603 1.0uF", Part Number=1276-1184-1-ND, Tolerance=10%
C6 C12 C13 C14 C16 C17 C23 C28 C31 C32 C39 C48 C49 C55 C61 C62 C63 C64 C66 C76 C81 C84 C85 C87 C89 C90 C92 C94 C95 C96 C97 C98 C99 C100 C195 C196 C200 C215 C217: library part ChipCap, "C0402 0.1uF", Part Number=1276-6720-1-ND, Tolerance=10%
C7 C15 C18 C26 C27 C34 C38 C43 C44 C45 C46 C59 C60 C74 C75 C78 C79 C80 C82 C86 C88 C91 C168 C189 C204 C206 C209: library part ChipCap, "C0805 10uF", Part Number=1276-6454-1-ND, Tolerance=10%
C8 C22 C41 C42 C67: library part ChipCap, "C0402 1.0nF", Part Number=1292-1246-1-ND, Tolerance=10%
C20 C21 C25 C69 C70 C77 C101 C102 C103 C104 C129 C190 C191 C208 C213: library part ChipCap, "C1206 47uF", Part Number=490-16268-1-ND, Tolerance=10%
C35 C65 C71 C93 C198 C199 C205 C218: library part ChipCap, "C0402 0.01uF", Part Number=311-1349-1-ND, Tolerance=10%
C36: library part CapFilmAxial, "Film Capacitor, axial lead", Part Number=MCO2B474G, Tolerance=2%
C37 C40 C53 C54: library part ChipCap, "C0402 1.0uF", Part Number=490-10017-1-ND, Tolerance=10%
C47: library part "CapPolypropylene ECQPZ", "Polypropylene Film Capacitor, radial lead", Part Number=399-13063-ND, Tolerance=2%
C50 C56: library part ChipCap, "Capacitor, surface mount"
C51 C52: library part ChipCap, "C0402 1.8nF", Part Number=399-17370-1-ND, Tolerance=10%
C57: library part ChipCap, "C0402 5.6nF", Part Number=1276-1578-1-ND, Tolerance=10%
C58: library part ChipCap, "C0402 2.7nF", Part Number=399-14439-1-ND, Tolerance=10%
C72 C73: library part ChipTantalum, "Tantalum capacitor, surface mount", Part Number=399-3908-1-ND, Tolerance=20%
C105 C106 C107 C108 C109 C110 C111 C112 C113 C117 C118 C119 C120 C121 C122 C170 C171 C172 C176 C186 C187 C188 C197: library part ChipCap, "C0603 4.7uF", Part Number=1276-2087-1-ND, Tolerance=10%
C114 C115 C116 C123 C124 C125 C126 C127 C128 C131 C132 C133 C134 C135 C136 C137 C138 C139 C140 C141 C142 C143 C144 C145 C146 C148 C149 C151 C152 C153 C154 C155 C156 C157 C158 C159 C160 C161 C162 C164 C165 C167 C177 C179 C183 C185: library part CMP-2010-00306-1, "C0201 0.47uF", Part Number=1276-6445-1-ND, Tolerance=10%
C163 C166 C169 C173 C174 C175 C178 C180 C181 C182: library part CMP-2010-00306-1, "C0201 0.1uF", Part Number=CL03A474MR3NNNC, Tolerance=10%
C193 C194: library part ChipCap, "C0402 0.22uF", Part Number=587-6021-1-ND, Tolerance=10%
D1 D2: library part CMP-2000-06604-1, "Ultra Low Forward Voltage Schottky Rectifier, 15 V, -55 to 100 degC, 2-Pin Molded, RoHS, Tape and Reel", Part Number=LSM115JE3/TR13CT-ND
DS1: "Panel mount LED", Supplier Part Number 1=L71517CT-ND
DS2: library part CMP-0245-00001-1, "2.1x0.7mm Right Angle SMT LED, 1.3mm Thickness, Green"
DS3: library part CMP-0245-00001-1, "2.1x0.7mm Right Angle SMT LED, 1.3mm Thickness, Red"
FL1 FL2 FL3 FL4 FL5: library part CMP-2000-05960-1, "Block Type EMIFIL(R) Reference Specification, 15 A, 25 V, -40 to 125 degC, 6-Pin THD, RoHS, Bulk", Part Number=490-5055-ND
FR1 FR2 FR3 FR4 FR5 FR6: library part BLM31PG121SN1, "ferrite bead, 120Ohm at 100MHz, 1206", Part Number=490-1056-1-ND
J1: "Plug Assembly, 37 Position, Right Angle, .318 Series", Part Number=A32104-ND, Supplier Part Number 1=AE10986-ND
J2: "fiber optic transceiver, 1.25GB/s, MM, LC, SFP", Part Number=A97430CT-ND
J3: "Connector", Part Number=WM10869-ND
J4: "Receptacle Assembly, 25 Position, Right Angle, .318 Series", Part Number=A32128-ND
J5: "SMA, PCB Mount, Right Angle", Part Number=2057-RF2-49B-T-00-50-G-HDW-ND
L1 L8: library part ChipInductor, "Inductor", Part Number=994-1008CS-101XJLC
L2 L5: library part CMP-11268-000008-1, "INDUCTOR, 2.2uH", Tolerance=20%
L3: library part CMP-11268-000008-1, "INDUCTOR, 4.7uH", Tolerance=20%
L4: library part CMP-11268-000008-1, "INDUCTOR, 3.3uH", Tolerance=20%
L6 L7: library part ChipInductor, "Inductor", Part Number=994-1008LS-102XJLB
LOGO1: library part LIGO_logo
P1: library part "09 18 108 9621", "Flat Cable Connector (IDC), PCB Transition Connector, 2 Rows, Solder Pin, 8 Contacts"
P2: library part Xilinx_JTAG_Header, "Xilinx JTAG header, 7-Pin, Dual row", Part Number=WM18863-ND
P3: library part CMP-0001-00030-1, "Golden finger, PCIeX1, Dual, Opposite, Pitch 1mm, 36-Position"
P4 P5: library part SAMTEC_QSE40, "Samtec hi-speed socket, 0.8mm, 80 pins", Part Number=SAM8124-ND
Q1 Q5 Q6: "FDV301N, Digital FET, N-channel, SOT23", Part Number=FDV301NCT-ND
Q2 Q3: library part CMP-1048-00670-1, "General Purpose Transistor, PNP Silicon, 3-Pin SOT-23, Pb-Free, Tape and Reel", Part Number=MMBT3906LT1GOSCT-ND
Q4: library part CMP-2000-07602-1, "Dual N-Channel (D-S) MOSFET, 100 V, 36.7 A, -55 to 150 degC, 8-Pin SMD, RoHS, Tape and Reel", Part Number=SI7252DP-T1-GE3CT-ND
R1 R2 R102 R184: library part ChipRes1, "R0402 20", Part Number=A127156CT-ND, Tolerance=0.1%
R3 R7 R15 R58 R176 R182: library part ChipRes1, "R0603 4.99k", Part Number=RR08P4.99KDCT-ND, Tolerance=0.1%
R4 R8 R9 R11 R13 R50 R51 R59 R60 R69 R70 R76 R77 R89 R90 R91 R123 R144 R167 R171 R172 R177 R183 R185 R188 R191 R196 R199 R201: library part ChipRes1, "R0402 10k", Part Number=RR05P10.0KDCT-ND, Tolerance=0.1%
R5 R6 R10 R12: library part ChipRes1, "R0603 220", Part Number=RR08P220DCT-ND, Tolerance=0.1%
R14 R121 R130 R141 R142 R160: library part ChipRes1, "R0402 100k", Part Number=RR05P100KDCT-ND, Tolerance=0.1%
R16 R168 R180 R192 R198: library part ChipRes1, "R0603 6.42k", Part Number=RR08P6.49KDCT-ND, Tolerance=0.1%
R17 R28 R34 R36 R61 R71 R74 R81 R94 R106 R118 R120 R147 R148 R202 R203: library part ChipRes1, "Resistor, surface mount", Tolerance=0.1%
R18 R20 R22 R26 R27 R30 R31 R35 R39 R103 R104 R145 R155 R156 R158 R159 R161 R162 R164 R165 R166 R173 R174 R175 R178 R179 R189 R197: library part ChipRes1, "R0603 100", Part Number=RR08P100DCT-ND, Tolerance=0.1%
R19 R45 R46 R47 R137 R140: library part ChipRes1, "R0603 1.0k", Part Number=RR08P1.0KDCT-ND, Tolerance=1%
R21 R29 R37 R87 R92 R95 R129 R186 R195 R200: library part ChipRes1, "R0603 1.0k", Part Number=RR08P1.0KDCT-ND, Tolerance=0.1%
R23 R24 R55 R56 R100: library part ChipRes1, "R0603 49.9", Part Number=RR08Q49.9DCT-ND, Tolerance=0.1%
R25 R38 R42 R109 R110 R111 R112 R113 R114 R131 R132 R133 R134 R135 R157: library part ChipRes1, "R0402 4.7k", Part Number=RR05P4.7KDCT-ND, Tolerance=0.1%
R32 R33 R40 R43 R44: library part ChipRes1, "R0402 1.8k", Part Number=RR05P1.8KDCT-ND, Tolerance=0.1%
R41 R107 R108: library part ChipRes1, "R0402 10", Part Number=A127127CT-ND, Tolerance=0.1%
R48 R49 R96 R97 R99 R143: library part ChipRes1, "R1206 10m", Part Number=273-PCS1206DR0100ETCT-ND, Tolerance=0.1%
R52: library part ChipRes1, "R0402 1.91k", Part Number=YAG4201CT-ND, Tolerance=0.1%
R53 R54: library part ChipRes1, "R0805 392", Part Number=P20236CT-ND, Tolerance=0.1%
R57 R98: library part ChipRes1, "R0805 22k", Part Number=RR12P22.0KDCT-ND, Tolerance=0.1%
R62 R72 R83 R117: library part ChipRes1, "R0402 2.0k", Part Number=RG10P2.00KDCT-ND, Tolerance=0.1%
R63 R73 R84 R85 R116 R119 R154: library part ChipRes1, "R0402 0", Part Number=541-2877-1-ND, Tolerance=0.1%
R64 R79: library part ChipRes1, "R0805 30k", Part Number=RR12P30.0KDCT-ND, Tolerance=0.1%
R65: library part ChipRes1, "R0402 15k", Part Number=RR05P15.0KDCT-ND, Tolerance=0.1%
R66: library part ChipRes1, "R0402 9.31k", Part Number=311-2336-1-ND, Tolerance=0.1%
R67: library part ChipRes1, "R0402 31.6k", Part Number=311-2272-1-ND, Tolerance=0.1%
R68: library part ChipRes1, "R0402 12.7k", Part Number=RNCF0402DTE12K7CT-ND, Tolerance=0.1%
R75: library part ChipRes1, "R0402 40.2k", Part Number=P18270CT-ND, Tolerance=0.1%
R78: library part ChipRes1, "R0402 21.5K", Part Number=RNCF0402DTE21K5CT-ND, Supplier Part Number 1=A127447CT-ND, Tolerance=0.1%
R80: library part ChipRes1, "R0402 37.4k", Part Number=YAG4250CT-ND, Tolerance=0.1%
R82: library part ChipRes1, "R0402 56.2k", Part Number=311-2303-1-ND, Tolerance=0.1%
R86 R88 R115 R126 R127 R128 R163 R194: library part ChipRes1, "R0402 7.15k", Part Number=YAG1478CT-ND, Tolerance=0.1%
R93: library part ChipRes1, "R0402 47k", Part Number=RG10P47KBCT-ND, Tolerance=0.1%
R101 R105: library part ChipRes1, "R0805 261", Part Number=P20214CT-ND, Tolerance=0.1%
R122: library part ChipRes1, "R0402 402k", Part Number=RMCF0402FT402KCT-ND, Tolerance=0.1%
R124: library part ChipRes1, "R0402 9.31k", Part Number=YAG4326CT-ND, Tolerance=0.1%
R125: library part ChipRes1, "R0402 301k", Part Number=RMCF0402FT301KCT-ND, Tolerance=0.1%
R136 R139 R149 R152 R181 R190 R193: library part ChipRes1, "R0402 49.9k", Part Number=RR05P49.9KDCT-ND, Tolerance=0.1%
R138 R151: library part ChipRes1, "R0402 300", Part Number=RR05P300DCT-ND, Tolerance=0.1%
R146: library part ChipRes1, "R0402 15", Part Number=A127144CT-ND, Tolerance=0.1%
R150: library part ChipRes1, "R0402 12.1k", Part Number=RR05P12.1KDCT-ND, Tolerance=0.1%
R153: library part ChipRes1, "R0402 133k", Part Number=A127523CT-ND, Tolerance=0.1%
R169: library part ChipRes1, "R0603 40.2k", Part Number=RR08P40.2KDCT-ND, Tolerance=0.1%
R170: library part ChipRes1, "R0603 3.01k", Part Number=RR08P3.01KDCT-ND, Tolerance=0.1%
R187: library part ChipRes1, "R0603 30.1k", Part Number=RR08P30.1KDCT-ND, Tolerance=0.1%
S1: "DIP Switch, 8 Position, SPST", Part Number=CKN6128CT-ND
S2: "Switch, SMD, 6mm", Part Number=SW262CT-ND
T1: library part TC1.5-52, "Transformer 1:4, wide band, 0.5-300 MHz", Part Number=TC1.5-52T
TP1 TP3 TP7 TP9 TP10 TP12 TP15 TP19 TP21 TP22 TP25: library part TP_POSITIVE, "Testpoint, red", Part Number=36-5000-ND
TP2 TP5: library part TP_NEGATIVE, "Testpoint, white", Part Number=36-5002-ND
TP4 TP6 TP8 TP13 TP14 TP18 TP20 TP23 TP24: library part TP_GND, "Testpoint, black", Part Number=36-5001-ND
TP11 TP16 TP17 TP26: library part TP_SIGNAL, "Testpoint, yellow", Part Number=36-5004-ND
U1 U5 U6 U8 U9: library part CMP-0944-00088-2, "Low Power, Precision Instrumentation Amplifier, -40 to 125 degC, 8-pin SOP (DGK8), Green (RoHS & no Sb/Br)", Part Number=296-23564-1-ND
U2: library part CMP-0798-00217-1, "1.8 to 5.5 V / 2.5 V, CMOS Low-Voltage 2.5 Ohm, 16-Channel Multiplexer, -40 to 85 degC, 28-pin SOP (RU-28), Tube", Part Number=ADG706BRUZ-REEL7CT-ND
U3: "Precision Rail-to-Rail Input and Ouput Operational Amplifier", Part Number=OP184FSZ-REELCT-ND
U4 U21 U24 U28: "Precision Rail-to-Rail Input and Output Operational Amplifier", Part Number=OP284ESZ-REEL7TR-ND
U7 U10: library part SN74AHCT04D, "Hex Inverter", Part Number=296-1218-1-ND
U11 U12: "16 bit DAC, 250kSPS, unipolar, serial", Part Number=AD5060BRJZ-1500RL7CT-ND
U13 U23: library part 74F74PC, "Dual D-Type Positive Edge-Triggered Flip-Flop", Part Number=296-1240-5-ND
U14: "Quad LVDS Receiver with 100 Ohm termination", Part Number=296-6901-5-ND
U15: "Quad-Bit Dual Supply Transceiver", Part Number=296-18056-1-ND
U16: library part CMP-0383-00019-1, "Artix-7 FPGA, 250 User I/Os, 4 GTP, 484-Ball BGA, Speed Grade 2, Commercial Grade, Pb-Free"
U17: library part CMP-0327-00205-3, "125 Mbps Enhanced Product Memorystick? Interconnect Extender Chipset with LVDS and LVTTL, 1 Tx and 4 Rx, -55 to +125 degC, 20-pin TSSOP (PW), Green (RoHS & no Sb/Br)", Part Number=296-19499-1-ND
U18: library part CMP-12948-000005-1, "IC FLASH 128M SPI 133MHZ 16SOIC", Part Number=1274-1001-ND
U19: "Switched capacitor voltage inverter", Part Number=LTC1144IS8#TRPBFCT-ND
U20: library part CMP-1329-00027-1, "MirrorBit Flash Non-Volatile Memory CMOS 3.0 Volt Core with Versatile I/O, Serial Peripheral Interface with Multi-I/O, 128 Mbit, 133 MHz, -40 to 85 degC, 8-Pin WSON (WNG008), RoHS, Tape and Reel", Part Number=428-4003-1-ND
U22: "16 bit ADC, 250kSPS, pseudo differential, serial", Part Number=AD7685ARMZRL7CT-ND
U25: Part Number=296-9845-1-ND
U26: "Artix 7 Power Supply", Part Number=ADP5050ACPZ-R7CT-ND
U27: library part VECTRON_C5310, "Voltage controlled crystal oscillator", Part Number=C5310-D105-SV033-RFL-B1-67.108864MHz
U29 U32: library part SN65LVDS100, "DIFF TRANSLATOR", Part Number=296-39184-1-ND
U30 U35 U39: library part SN65LVDT2DBV, "Single LVDS Receiver with 100 Ohm termination", Part Number=296-6896-1-ND
U31: library part ADR292ER, "Low-Noise Micropower Precision Voltage Reference", Part Number=ADR425ARZ-ND
U33: library part SN65LVDS100, "DIFF TRANSLATOR", Part Number=296-15391-5-ND
U34 U43: "Positive voltage regulator", Part Number=LT1763CS8#PBF-ND
U36 U37: "20V, 500mA, Ultralow Noise, / Ultrahigh PSRR Linear Regulator", Part Number=LT3045IMSE-1#PBF-ND
U38: library part SN74LVC1T45, "Single-Bit Dual Supply Transceiver", Part Number=296-17992-1-ND
U40: library part CMP-0367-00169-1, "3.3 V, 50 ppm / degC, 50 uA Series (Bandgap) Voltage Reference, -40 to 125 degC, 3-pin SOT-23 (DBZ), Green (RoHS & no Sb/Br)", Part Number=296-52689-1-ND
U41: library part CMP-0476-01338-1, "200 mA, Low Noise, Low Dropout Negative Micropower Regulator, -1.9 to -20 V Vin, -5 V Vout, 5-pin SOT23 (S5-5), -40 to 125 degC, Pb-Free, Mini Tape and Reel", Part Number=LT1964ES5-5#TRPBFCT-ND
U42: library part CMP-0784-00214-1, "Ultraprecision, Low Noise, XFET(R) Voltage Reference, 2.5 V Output, 4.5 to 18 V Supply, Industrial, 8-pin SOIC (R-8), Tube", Part Number=ADR421ARZ-REEL7CT-ND
W1: library part NetTie1, "Tie two nets together"
W2: library part NetTie1_small, "Tie two nets together"
Y1: library part CMP-06255-000005-1, "MEMS OSC XO 25.0000MHZ CMOS SMD", Part Number=576-4966-5-ND

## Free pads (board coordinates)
  round 190 hole 125: 0(-684.25,-1113.39) 0(-684.25,1886.61) 0(1315.75,-1113.39) 0(1315.75,1886.61)
  round 113.39 hole 125.2 unplated: MH1(-2942.91,-1954.72) MH2(-2933.07,1407.48)

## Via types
v1: diameter 19, hole 10, Top Layer to Bottom Layer, tented both sides, 667 vias
v2: diameter 20, hole 10, Top Layer to Bottom Layer, tented both sides, 248 vias
v3: diameter 16, hole 10, Top Layer to Bottom Layer, tented both sides, 191 vias
v4: diameter 12, hole 6, Top Layer to Bottom Layer, tented both sides, 85 vias
v5: diameter 19.68, hole 10, Top Layer to Bottom Layer, tented both sides, 50 vias
v6: diameter 17.72, hole 10, Top Layer to Bottom Layer, tented both sides, 19 vias
v7: diameter 19, hole 10, Top Layer to Bottom Layer, 15 vias
v8: diameter 23.62, hole 10, Top Layer to Bottom Layer, tented both sides, 14 vias
v9: diameter 20, hole 10, Top Layer to Bottom Layer, 11 vias
v10: diameter 16, hole 10, Top Layer to Bottom Layer, 3 vias
v11: diameter 22, hole 12, Top Layer to Bottom Layer, tented both sides, 2 vias
v12: diameter 19.02, hole 10, Top Layer to Bottom Layer, tented both sides, 1 vias

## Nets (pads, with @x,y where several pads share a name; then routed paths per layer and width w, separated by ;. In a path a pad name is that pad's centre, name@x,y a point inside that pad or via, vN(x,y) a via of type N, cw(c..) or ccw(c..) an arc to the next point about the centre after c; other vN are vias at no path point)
3.3Vaux: P3.B10
12V: C28.1 C29.1 C43.1 C44.1 C59.1 C60.1 C77.2 C80.1 FL2.1 FL5.1 P5.77 P5.79 R37.2 R47.2 R99.2 R137.1 R142.1 R143.2 TP19.1 U19.8 U21.8 U26.4 U26.9 U26.24 U26.25 U26.35 U26.36 | length 3105.1
  Top Layer w10: P5.77@977.16,1673.83 v1(977.16,1734.28) ; P5.79@1008.65,1673.83 v1(1008.65,1734.28) ; R37.2@1061.02,-1692.91 1059.25,-1691.14 U19.8@1059.25,-1618.11 1066.06,-1611.3 1066.06,-1579.61 1102.29,-1543.38 1139.69,-1543.38 C28.1@1141.72,-1541.34 ; U21.8@1204.72,-488.39 1208.75,-488.39 1215.04,-494.68 1215.04,-518.19 v2(1228.35,-531.5) 1231.05,-531.5 1236.05,-536.5 1251.06,-536.5 C29.1@1265.75,-551.18 ; R47.2@1568.9,-370.08 1581.16,-382.34 ccw(c1628.78,-334.73) 1628.78,-402.07 cw(c1628.78,-529.58) 1718.94,-439.41 1832.92,-553.39 ccw(c1903.63,-482.68) 1903.63,-582.68 2385.13,-582.68 ccw(c2385.13,-482.68) 2455.84,-553.39 2620.99,-388.23 cw(c2702.84,-470.08) 2702.84,-354.33 2832.68,-354.33 ccw(c2832.68,-336.18) 2850.83,-336.18 2872.48,-336.18 ccw(c2872.48,-307.09) R99.2@2901.57,-307.09 2927.8,-280.86 2927.8,-103.7 FL5.1@2933.07,-98.43 ; C43.1@1889.76,-1250.97 1890.75,-1249.99 U26.9@1961.69,-1249.99 ; C44.1@1889.76,-1152.55 1890.75,-1151.56 U26.4@1961.69,-1151.56 ; U26.24@2214.64,-1335.62 2241.14,-1335.62 ; U26.25@2241.14,-1309.06 2241.14,-1335.62 ; U26.35@2241.14,-1112.2 U26.36@2241.14,-1092.52 ; U26.36@2250.9,-1092.44 2251.18,-1092.17 2258.23,-1092.17 2268.78,-1081.61 2268.78,-1073.74 2271.16,-1071.36 2271.65,-1071.36 2271.65,-1056.02 2282.41,-1045.27 C60.1@2291.34,-1045.27 ; 2265.81,-1335.62 2241.14,-1335.62 ; C59.1@2269.76,-1341.61 C59.1@2287.4,-1359.25
  Bottom Layer w10: R143.2@-196.85,-1511.81 R143.2@-194.96,-1511.81 ; R142.1@-171.26,-1614.17 -171.26,-1535.52 R143.2@-194.96,-1511.81 ; R137.1@-39.37,-1312.99 -39.37,-1383 -59.06,-1402.69 FL2.1@-59.06,-1417.32 -124.25,-1482.52 cw(c-194.96,-1411.81) R143.2@-194.96,-1511.81 ; FL5.1@2933.07,-98.43 2933.07,-105.88 2975.47,-148.28 2975.47,-176.26 2976.38,-177.17 C77.2@2976.38,-275.59
  other v2: 1125.98,-1590.55 1157.48,-1590.55
  other v4: 2267.72,-1327.6 2287.4,-1327.6 2307.09,-1327.6 1854.33,-1267.72 1850.39,-1157.47 1850.39,-1136.8 2272.76,-1071.36 2291.34,-1071.36 2311.02,-1071.36
+3.3V: C195.1 P3.A9 P3.A10 P3.B8 R148.2 U38.6 | length 1217.3
  Top Layer w10: P3.B8@-1155.51,-2185.04 -1155.51,-2088.58 -1137.55,-2070.62 v6(-1116.14,-2070.62)
  Int7 (Sign) w10: v6(-1116.14,-2070.62) -1116.14,-1927.25 cw(c-1016.14,-1927.25) -1086.85,-1856.54 v6(-773.62,-1543.31)
  Bottom Layer w10: P3.A9@-1116.14,-2185.04 v6(-1116.14,-2070.62) -1094.35,-2070.62 -1076.77,-2088.2 P3.A10@-1076.77,-2185.04 ; C195.1@-820.87,-1437.01 -777.48,-1437.01 -773.62,-1440.87 v6(-773.62,-1543.31)
A12V: C72.1 C73.1 C89.2 FL5.2 U34.5 U34.8 | length 2329.3
  Top Layer w10: FL5.2@2933.07,98.43 3157.48,322.83 C73.1@3157.48,808.11
  Bottom Layer w10: U34.8@1677.17,62.8 1779.33,62.8 ccw(c1779.33,120.08) 1836.61,120.08 C89.2@1836.61,137.8 ; U34.5@1677.17,212.8 1779.33,212.8 cw(c1779.33,155.51) 1836.61,155.51 C89.2@1836.61,137.8 ; 1929.1,118.14 ccw(c1881.61,70.59) 1881.61,137.8 C89.2@1836.61,137.8 ; 1929.17,118.08 ccw(c1976.66,165.63) 1976.64,98.43 2070.87,98.43 FL5.2@2933.07,98.43
AGND: C30.1 C33.1 C34.2 C38.1 C39.1 C55.1 C63.1 C64.1 C66.1 C67.2 C72.2 C73.2 C82.2 C83.1 C89.1 C91.2 FL5.4 FL5.5 FL5.6 R91.2 R92.2 R129.2 U22.4 U22.5 U24.4 U27.3 U28.4 U31.4 U34.3 U34.6 U34.7 | length 855
  Top Layer w10: U22.4@1379.92,157.48 v2(1318.9,157.48) 1320.43,159.01 1320.43,171.31 1326.28,177.17 U22.5@1379.92,177.17 ; 1594.49,157.48 1601.3,164.29 1601.3,176.3 1637.8,212.8 U24.4@1669.29,212.8 ; v2(2023.62,358.27) 2090.35,358.27 U28.4@2090.55,358.07 ; v2(2283.46,-154.33) 2416.14,-154.33 cw(c2416.14,-218.5) R92.2@2480.31,-218.5 ; C67.2@2557.09,-218.5 ccw(c2557.09,-216.54) C67.2@2559.06,-216.54
  Bottom Layer w10: U34.3@1472.44,162.8 U34.6@1677.17,162.8 ; v2(1574.8,118.11) 1580.12,112.8 U34.7@1677.17,112.8
  other v2: 1771.65,-354.33 2527.56,-236.22 2527.56,-208.66 1480.32,-94.49 1519.68,-94.49 1500,-74.8 1539.37,-74.8 1736.22,118.11 1555.12,137.8 1594.49,137.8 1574.8,157.48 1736.22,157.48 2342.52,169.29 1299.21,177.23 1318.9,196.85 2342.52,196.85 1405.51,283.46 2295.28,303.15 1405.51,307.09 2275.59,322.83 2314.96,322.83 2362.2,322.83 2519.68,618.11 2519.68,641.73 2291.34,673.23 2314.96,673.23 2893.7,688.98 2933.07,688.98 2519.68,696.85 2874.02,708.66 2913.39,708.66 2519.68,720.47 2893.7,728.35 2933.07,728.35
AVCC: C163.1 C166.2 C168.2 C169.1 C174.2 C175.1 R141.2 R182.1 U16.D6 U16.D10 U16.E8 U16.F7 U16.F9 U36.10 U36.11 U36.12 | length 2103.7
  Top Layer w10: v1(-314.96,-236.22) U16.D6@-295.28,-216.54 ; v1(-314.96,-78.74) U16.D10@-295.28,-59.06 ; v1(-275.59,-157.48) U16.E8@-255.91,-137.8 ; v1(-236.22,-118.11) U16.F9@-216.54,-98.43 ; U16.F7@-216.54,-177.17 v1(-196.85,-157.48)
  Int3 (Sign) w10: v1(-905.51,-314.96) -875.75,-285.19 cw(c-805.04,-355.91) -805.04,-255.91 -536.42,-255.91 -362.48,-255.91 ccw(c-362.48,-188.7) v1(-314.96,-236.22)
  Bottom Layer w10: R182.1@-1948.82,-171.26 -1948.82,-173.23 -1856.06,-265.99 ccw(c-1785.35,-195.28) -1785.35,-295.28 -953.04,-295.28 cw(c-953.04,-362.48) v1(-905.51,-314.96) ; -255.91,-648.01 -253.56,-650.35 U36.11@-199.24,-650.35 ; C168.2@-255.91,-582.68 -255.91,-625.98 ; R141.2@-205.71,-787.4 R141.2@-202.76,-787.4 ; U36.10@-204.11,-676.18 -245.08,-676.18 -255.91,-665.35 -255.91,-650.35 -255.91,-645.67 -255.91,-625.98 ; U36.12@-204.11,-625 -254.92,-625 -255.91,-625.98
  other v1: -196.85,-814.96 -236.22,-594.49 -236.22,-555.12
AVCC1V8: C18.1 C37.2 FR5.1 R58.2 R171.1 TP9.1 U26.7 | length 820.8
  Top Layer w10: C37.2@1734.74,-1138.28 1734.74,-1142.21 1743.52,-1150.99 1748.38,-1150.99 1749.38,-1151.99 1803.97,-1151.99 1842.73,-1190.75 1920.91,-1190.75 1940.78,-1210.62 U26.7@1961.69,-1210.62
  Bottom Layer w10: R171.1@-1830.71,-171.26 -1807.28,-171.26 ccw(c-1807.28,-147.02) -1790.15,-164.17 -1536.39,89.6 ; -1536.36,89.62 cw(c-1496.06,49.27) -1496.06,106.3 -1477.24,106.3 -1476.17,107.36 -1424.13,107.36 FR5.1@-1393.7,137.8
  other v3: -1468.5,125.98 -1437.01,125.98 -1452.76,141.73
  other v4: 1663.38,-1149.1 1663.38,-1126.96
AVTT: C173.1 C178.2 C180.2 C181.2 C182.2 C189.2 R145.2 R153.2 R176.1 U16.B5 U16.B7 U16.B9 U16.B11 U16.C4 U16.C8 U37.10 U37.11 U37.12 | length 1422.6
  Top Layer w10: v1(-393.7,-275.59) U16.B5@-374.02,-255.91 ; v7(-393.7,-196.85) U16.B7@-374.02,-177.17 ; v1(-393.7,-118.11) U16.B9@-374.02,-98.43 ; v1(-393.7,-39.37) U16.B11@-374.02,-19.68 ; v1(-354.33,-314.96) U16.C4@-334.65,-295.28 ; v1(-354.33,-157.48) U16.C8@-334.65,-137.8
  Bottom Layer w10: R176.1@-1889.76,-171.26 -1889.76,-173.23 -1863.87,-199.12 ccw(c-1793.16,-128.41) -1793.16,-228.41 -1129.99,-228.41 -1129.92,-228.35 -1039.37,-228.35 ccw(c-1039.37,-137.8) -948.82,-137.8 ; U37.10@-754.92,-91.17 -754.92,-51.38 -746.85,-43.31 -729.33,-43.31 ; U37.11@-729.33,-91.17 -729.33,-43.31 ; U37.12@-704.72,-98.43 R145.2@-647.64,-98.43 ; U37.12@-703.74,-91.17 -703.74,-51.38 -711.81,-43.31 -729.33,-43.31
  other v1: -964.57,-125.98 -933.07,-125.98 -647.64,-66.93
BACKPLANE.CLK0_N: J1.21 U16.C20 | length 2727.2
  Top Layer w5: v1(-354.33,354.33) U16.C20@-334.65,334.65
  Int2 (Sign) w3: J1.21@-2944.69,557.09 cw(c-2937.59,549.99) -2937.59,560.03 -2891.1,560.03 cw(c-2891.1,537.99) -2875.52,553.57 ccw(c-2859.94,569.15) -2859.94,547.12 -765.7,547.12 cw(c-765.7,447.12) -694.99,517.83 -578.86,401.69 ccw(c-502.53,478.02) -502.53,370.08 -346.52,370.08 cw(c-346.52,362.2) -338.65,362.2 cw(c-346.52,362.2) -346.52,354.33 v1(-354.33,354.33)
BACKPLANE.CLK0_P: J1.2 U16.D20 | length 2733.8
  Top Layer w5: v1(-314.96,354.33) U16.D20@-295.28,334.65
  Int2 (Sign) w3: J1.2@-2832.87,611.61 -2875.44,569.05 ccw(c-2873.32,566.93) -2876.32,566.93 ccw(c-2873.32,566.93) -2875.44,564.8 ccw(c-2852.05,588.19) -2852.05,555.12 -765.67,555.12 cw(c-765.67,447.2) -689.36,523.51 -573.22,407.37 ccw(c-502.51,478.08) -502.51,378.08 -346.52,378.08 cw(c-346.52,362.2) -330.65,362.2 ccw(c-322.77,362.2) -322.77,354.33 v1(-314.96,354.33)
BACKPLANE.CLK1_N: J1.30 U16.B16 | length 3555
  Top Layer w5: J1.30@-2944.69,-424.41 -2903.53,-383.26 ccw(c-2907.07,-379.72) -2902.07,-379.72 ccw(c-2907.07,-379.72) -2903.53,-376.19 ; -2903.57,-376.15 cw(c-2894.46,-367.04) -2907.34,-367.04 -2907.34,-366.92 cw(c-2894.51,-366.92) -2903.58,-357.85 -2888.23,-342.5 cw(c-2811.94,-418.8) -2811.94,-310.9 -2722.17,-310.9 ccw(c-2722.17,-210.9) -2622.17,-210.9 -2622.17,368.5 cw(c-2514.17,368.5) -2514.17,476.5 -647.75,476.5 cw(c-647.75,336.5) -507.75,336.5 -507.75,271.53 ccw(c-436.92,271.53) -436.92,200.7 -406.92,200.7 cw(c-406.92,183.55) -389.77,183.55 -389.77,168.53 ccw(c-382.72,168.53) -382.72,161.48 ccw(c-382.72,170.18) -374.02,170.18 U16.B16@-374.02,177.17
